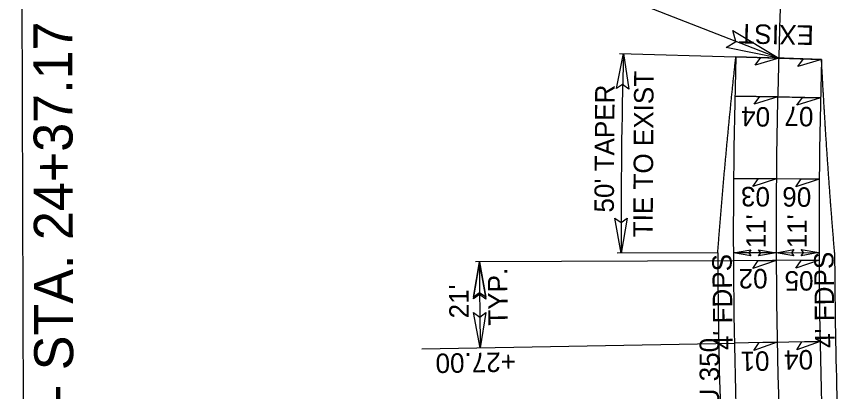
# Model space of a CAD drawing. Extents: x 1373164 to 1374172, y 550391 to 553180.
# Drawn here: x 1373510 to 1373722, y 551876.6 to 551972.9 of the extents above; entities that cross this region are included whole.
import ezdxf

# ---------------------------------------------------------------- set-up
doc = ezdxf.new("R2010")
doc.units = 0
for name, color, linetype in [('Default Symbol Cogo Elevation', 7, 'Continuous'), ('Exist Building Cogo Number', 7, 'Continuous'), ('Exist Building Cogo Point CELL', 7, 'Continuous'), ('Exist Other Culture Fence Line Cogo Number', 7, 'Continuous'), ('Exist Other Culture Fence Line Cogo Point CELL', 7, 'Continuous'), ('Exist Other Culture Gate Cogo Comment', 7, 'Continuous'), ('Exist Other Culture Gate Cogo Point CELL', 7, 'Continuous'), ('Exist Roads EOP Other Cogo Elevation', 7, 'Continuous'), ('Exist Structure Major Deck Tunnel Box Culvert Cogo Point CELL', 7, 'Continuous'), ('Exist Structure Minor Pipes RCP 18 Inch Cogo Number', 7, 'Continuous'), ('Exist Utilities Sanitary Sewer Manhole Cogo Elevation', 7, 'Continuous')]:
    doc.layers.add(name, color=color, linetype=linetype)

msp = doc.modelspace()

# ---------------------------------------------------------------- linework, layer by layer
at = {"layer": 'Default Symbol Cogo Elevation'}
msp.add_line((1373694.63, 551962.58), (1373716.62, 551961.94), dxfattribs=at)
for radius in [1546, 1524]:
    msp.add_arc((1375239.98, 551917.59), radius, 178.33248, 182.95848, dxfattribs=at)
at = {"layer": 'Exist Building Cogo Number'}
for radius in [1550, 1520]:
    msp.add_arc((1375239.98, 551917.59), radius, 180.19879, 182.95848, dxfattribs=at)
for points in [[(1373689.99, 551912.22), (1373690.04, 551912.9), (1373690.09, 551913.58), (1373690.14, 551914.26), (1373690.2, 551914.95), (1373690.25, 551915.63), (1373690.3, 551916.31), (1373690.36, 551916.99), (1373690.41, 551917.68), (1373690.47, 551918.36), (1373690.52, 551919.04), (1373690.57, 551919.72), (1373690.63, 551920.4), (1373690.69, 551921.09), (1373690.74, 551921.77), (1373690.8, 551922.45), (1373690.85, 551923.13), (1373690.91, 551923.81), (1373690.97, 551924.49), (1373691.02, 551925.18), (1373691.08, 551925.86), (1373691.14, 551926.54), (1373691.2, 551927.22), (1373691.26, 551927.9), (1373691.32, 551928.58), (1373691.37, 551929.26), (1373691.43, 551929.94), (1373691.49, 551930.63), (1373691.55, 551931.31), (1373691.61, 551931.99), (1373691.67, 551932.67), (1373691.73, 551933.35), (1373691.8, 551934.03), (1373691.86, 551934.71), (1373691.92, 551935.39), (1373691.98, 551936.07), (1373692.04, 551936.75), (1373692.11, 551937.44), (1373692.17, 551938.12), (1373692.23, 551938.8), (1373692.3, 551939.48), (1373692.36, 551940.16), (1373692.42, 551940.84), (1373692.49, 551941.52), (1373692.55, 551942.2), (1373692.62, 551942.88), (1373692.68, 551943.56), (1373692.75, 551944.24), (1373692.81, 551944.92), (1373692.88, 551945.6), (1373692.95, 551946.28), (1373693.01, 551946.96), (1373693.08, 551947.64), (1373693.15, 551948.32), (1373693.22, 551949), (1373693.28, 551949.68), (1373693.35, 551950.36), (1373693.42, 551951.04), (1373693.49, 551951.72), (1373693.56, 551952.4), (1373693.63, 551953.08), (1373693.7, 551953.76), (1373693.77, 551954.44), (1373693.84, 551955.11), (1373693.91, 551955.79), (1373693.98, 551956.47), (1373694.05, 551957.15), (1373694.12, 551957.83), (1373694.2, 551958.51), (1373694.27, 551959.19), (1373694.34, 551959.87), (1373694.41, 551960.55), (1373694.49, 551961.23), (1373694.63, 551962.58)], [(1373719.99, 551912.32), (1373719.93, 551912.99), (1373719.88, 551913.66), (1373719.82, 551914.33), (1373719.76, 551915), (1373719.71, 551915.67), (1373719.66, 551916.34), (1373719.6, 551917), (1373719.55, 551917.67), (1373719.49, 551918.34), (1373719.44, 551919.01), (1373719.39, 551919.68), (1373719.33, 551920.35), (1373719.28, 551921.02), (1373719.23, 551921.69), (1373719.18, 551922.36), (1373719.12, 551923.03), (1373719.07, 551923.7), (1373719.02, 551924.37), (1373718.97, 551925.04), (1373718.92, 551925.71), (1373718.87, 551926.38), (1373718.82, 551927.05), (1373718.77, 551927.72), (1373718.72, 551928.39), (1373718.67, 551929.06), (1373718.62, 551929.73), (1373718.57, 551930.4), (1373718.53, 551931.07), (1373718.48, 551931.74), (1373718.43, 551932.41), (1373718.38, 551933.08), (1373718.33, 551933.75), (1373718.29, 551934.42), (1373718.24, 551935.09), (1373718.2, 551935.76), (1373718.15, 551936.43), (1373718.1, 551937.1), (1373718.06, 551937.77), (1373718.01, 551938.44), (1373717.97, 551939.11), (1373717.92, 551939.78), (1373717.88, 551940.46), (1373717.84, 551941.13), (1373717.79, 551941.8), (1373717.75, 551942.47), (1373717.71, 551943.14), (1373717.66, 551943.81), (1373717.62, 551944.48), (1373717.58, 551945.15), (1373717.54, 551945.82), (1373717.5, 551946.49), (1373717.46, 551947.17), (1373717.41, 551947.84), (1373717.37, 551948.51), (1373717.33, 551949.18), (1373717.29, 551949.85), (1373717.25, 551950.52), (1373717.21, 551951.19), (1373717.18, 551951.87), (1373717.14, 551952.54), (1373717.1, 551953.21), (1373717.06, 551953.88), (1373717.02, 551954.55), (1373716.98, 551955.22), (1373716.95, 551955.9), (1373716.91, 551956.57), (1373716.87, 551957.24), (1373716.84, 551957.91), (1373716.8, 551958.58), (1373716.76, 551959.25), (1373716.73, 551959.93), (1373716.69, 551960.6), (1373716.62, 551961.94)]]:
    msp.add_spline(points, degree=3, dxfattribs=at)
at = {"layer": 'Exist Building Cogo Point CELL'}
msp.add_line((1373705.63, 551962.26), (1373700.63, 551962.41), dxfattribs=at)
at = {"layer": 'Exist Other Culture Fence Line Cogo Number'}
msp.add_line((1373694.04, 551931.37), (1373705.04, 551931.27), dxfattribs=at)
at = {"layer": 'Exist Other Culture Fence Line Cogo Point CELL'}
for p, q in [((1373705.63, 551962.26), (1373694.63, 551962.58)), ((1373716.62, 551961.94), (1373704.63, 551962.29)), ((1373694.37, 551952.51), (1373705.37, 551952.27)), ((1373705.37, 551952.27), (1373694.37, 551952.51)), ((1373716.37, 551952.02), (1373704.37, 551952.29)), ((1373705.37, 551952.27), (1373716.37, 551952.02)), ((1373705.04, 551931.27), (1373694.04, 551931.37)), ((1373716.04, 551931.17), (1373704.04, 551931.28)), ((1373705, 551910.27), (1373694, 551910.22)), ((1373716, 551910.32), (1373704, 551910.26)), ((1373705.24, 551889.27), (1373694.24, 551889.07)), ((1373716.24, 551889.47), (1373704.24, 551889.25))]:
    msp.add_line(p, q, dxfattribs=at)
for points in [[(1373705.63, 551962.26), (1373699.57, 551960.44), (1373701.01, 551962.4)], [(1373716.62, 551961.94), (1373710.57, 551960.12), (1373712, 551962.08)], [(1373705.37, 551952.27), (1373699.33, 551950.4), (1373700.75, 551952.37)], [(1373716.37, 551952.02), (1373710.32, 551950.15), (1373711.74, 551952.12)], [(1373705.04, 551931.27), (1373699.02, 551929.32), (1373700.42, 551931.31)], [(1373716.04, 551931.17), (1373710.02, 551929.22), (1373711.41, 551931.21)], [(1373705, 551910.27), (1373699.01, 551908.24), (1373700.37, 551910.25)], [(1373716, 551910.32), (1373710.01, 551908.29), (1373711.37, 551910.3)], [(1373705.24, 551889.27), (1373699.28, 551887.16), (1373700.62, 551889.19)], [(1373716.24, 551889.47), (1373710.28, 551887.36), (1373711.61, 551889.39)]]:
    msp.add_lwpolyline(points, close=True, dxfattribs=at)
at = {"layer": 'Exist Roads EOP Other Cogo Elevation'}
msp.add_arc((1375239.98, 551917.59), 1535, 171.71033, 182.95848, dxfattribs=at)
at = {"layer": 'Exist Structure Major Deck Tunnel Box Culvert Cogo Point CELL'}
for points in [[(1373693.89, 551969.33), (1373705.63, 551962.26), (1373692.11, 551964.95), (1373694.59, 551966.56)], [(1373693.89, 551969.33), (1373705.63, 551962.26), (1373692.11, 551964.95), (1373694.59, 551966.56)], [(1373663.99, 551954.45), (1373665.79, 551963.4), (1373667.14, 551954.31), (1373665.57, 551955.5)], [(1373663.99, 551954.45), (1373665.79, 551963.4), (1373667.14, 551954.31), (1373665.57, 551955.5)], [(1373666.7, 551921.14), (1373665.2, 551912.13), (1373663.55, 551921.17), (1373665.16, 551920.03)], [(1373666.7, 551921.14), (1373665.2, 551912.13), (1373663.55, 551921.17), (1373665.16, 551920.03)], [(1373698.49, 551911.47), (1373693.99, 551912.23), (1373698.51, 551913.05), (1373697.94, 551912.24)], [(1373698.49, 551911.47), (1373693.99, 551912.23), (1373698.51, 551913.05), (1373697.94, 551912.24)], [(1373700.49, 551913.03), (1373704.99, 551912.27), (1373700.47, 551911.45), (1373701.04, 551912.26)], [(1373709.49, 551911.51), (1373704.99, 551912.27), (1373709.51, 551913.08), (1373708.94, 551912.28)], [(1373711.41, 551913.07), (1373715.91, 551912.31), (1373711.39, 551911.49), (1373711.96, 551912.29)], [(1373627.29, 551900.9), (1373628.81, 551909.91), (1373630.44, 551900.86), (1373628.84, 551902.01)], [(1373627.29, 551900.4), (1373628.81, 551909.4), (1373630.44, 551900.36), (1373628.84, 551901.5)], [(1373630.43, 551896.89), (1373629.03, 551887.86), (1373627.28, 551896.89), (1373628.9, 551895.76)], [(1373630.43, 551896.89), (1373629.03, 551887.86), (1373627.28, 551896.89), (1373628.9, 551895.76)]]:
    msp.add_lwpolyline(points, close=True, dxfattribs=at)
at = {"layer": 'Exist Utilities Sanitary Sewer Manhole Cogo Elevation'}
for p, q in [((1373511.82, 551853.37), (1373511.4, 552008.55)), ((1373664.79, 551963.45), (1373694.63, 551962.58)), ((1373689.99, 551912.22), (1373664.2, 551912.13)), ((1373704.99, 551912.27), (1373693.99, 551912.23)), ((1373704.99, 551912.27), (1373715.91, 551912.31)), ((1373694, 551910.22), (1373627.81, 551909.9)), ((1373614.06, 551887.59), (1373694.24, 551889.07))]:
    msp.add_line(p, q, dxfattribs=at)
msp.add_lwpolyline([(1373705.63, 551962.26), (1373382.89, 552088.01), (1373383.12, 551828.23)], dxfattribs=at)
for centre, start, end in [((1375230.18, 551919.66), 178.39772, 180.27575), ((1375193.8, 551914.75), 180.17741, 180.98441)]:
    msp.add_arc(centre, 1565, start, end, dxfattribs=at)

# ---------------------------------------------------------------- texts
at = {"layer": 'Exist Other Culture Gate Cogo Comment'}
msp.add_text('GRAU 350', height=5, rotation=90, dxfattribs=at).set_placement((1373690.33, 551858.07))
at = {"layer": 'Exist Other Culture Gate Cogo Point CELL'}
for s, rotation, p in [('EXIST', 178.7057, (1373714.72, 551970.61)), ('04', 178.7057, (1373703.49, 551949.63)), ('07', 178.7057, (1373714.61, 551949.69)), ('03', 179.4896, (1373703.41, 551929.13)), ('06', 179.4896, (1373714.02, 551929.06)), ('02', 180.2734, (1373702.77, 551908.12)), ('05', 180.2734, (1373714.57, 551907.56)), ('01', 181.0573, (1373703.23, 551886.98)), ('04', 181.0573, (1373714.42, 551887.32))]:
    msp.add_text(s, height=5, rotation=rotation, dxfattribs=at).set_placement(p)
at = {"layer": 'Exist Structure Minor Pipes RCP 18 Inch Cogo Number'}
msp.add_text('-L- STA. 24+37.17', height=10, rotation=90.1567, dxfattribs=at).set_placement((1373524.6, 551862.03))
at = {"layer": 'Exist Utilities Sanitary Sewer Manhole Cogo Elevation'}
for s, rotation, p in [('TIE TO EXIST', 89.6486, (1373673.28, 551916.24)), ("50' TAPER", 89.6486, (1373663.32, 551922.58)), ("11'", 90, (1373702.3, 551913.4)), ("11'", 90, (1373712.85, 551913.4)), ("4' FDPS", 90.7219, (1373720, 551887.86)), ("4' FDPS", 90.7656, (1373693.87, 551887.29)), ('TYP.', 90.6537, (1373636.12, 551893.57)), ("21'", 90.6537, (1373626.1, 551895.45)), ('+27.00', 181.0573, (1373638.14, 551886.73))]:
    msp.add_text(s, height=5, rotation=rotation, dxfattribs=at).set_placement(p)

doc.saveas('drawing.dxf')
